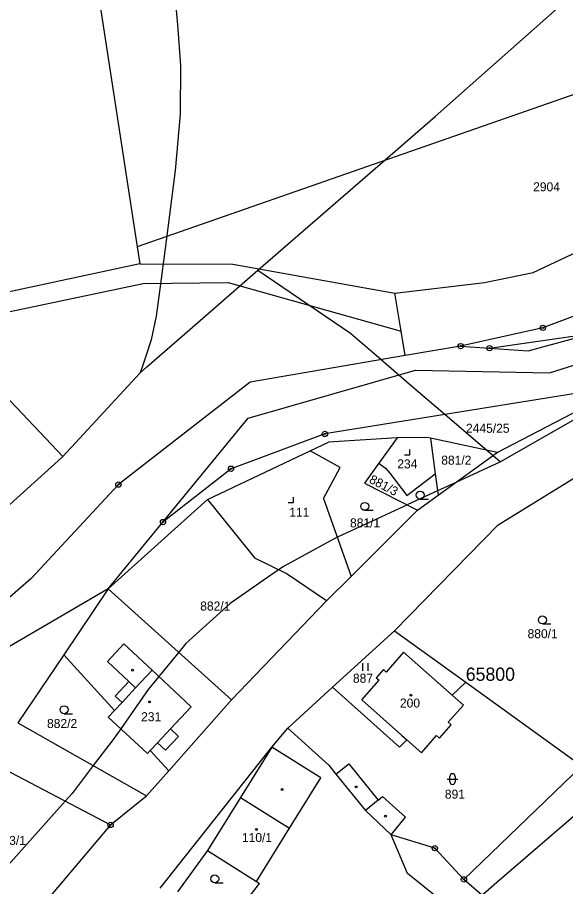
# Model space of a CAD drawing. Extents: x -546762 to -540209, y -1046851 to -1035694.
# Drawn here: x -542845.1 to -542741.6, y -1040039.2 to -1039875.2 of the extents above; entities that cross this region are included whole.
import ezdxf

# ---------------------------------------------------------------- set-up
doc = ezdxf.new("R2010")
doc.units = 0
for name, color, linetype in [('Vrstva 1', 7, 'Continuous'), ('Vrstva 18', 7, 'Continuous'), ('Vrstva 19', 7, 'Continuous'), ('Vrstva 24', 7, 'Continuous'), ('Vrstva 25', 7, 'Continuous'), ('Vrstva 3', 7, 'Continuous'), ('Vrstva 37', 7, 'Continuous'), ('Vrstva 4', 7, 'Continuous'), ('Vrstva 52', 7, 'Continuous'), ('Vrstva 53', 7, 'Continuous'), ('Vrstva 6', 7, 'Continuous')]:
    doc.layers.add(name, color=color, linetype=linetype)

msp = doc.modelspace()

# ---------------------------------------------------------------- linework, layer by layer
at = {"layer": 'Vrstva 1'}
for p, q in [((-542755.98, -1039937.61), (-542739.34, -1039935.24)), ((-542761.42, -1039937.23), (-542755.98, -1039937.61)), ((-542755.98, -1039937.61), (-542748.71, -1039938.12)), ((-542739.39, -1039946.11), (-542787.04, -1039953.79)), ((-542817.6, -1039970.43), (-542801.51, -1039950.85)), ((-542787.04, -1039953.79), (-542804.76, -1039960.36)), ((-542804.76, -1039960.36), (-542817.6, -1039970.43)), ((-542827.95, -1039983.03), (-542817.6, -1039970.43)), ((-542760.47, -1040000.62), (-542763, -1040003.11)), ((-542763, -1040003.11), (-542764.66, -1040001.64)), ((-542760.9, -1040004.95), (-542763, -1040003.11)), ((-542763.76, -1040008.2), (-542760.9, -1040004.95)), ((-542765.4, -1040011.19), (-542763.2, -1040008.7)), ((-542763.2, -1040008.7), (-542763.76, -1040008.2)), ((-542772.95, -1040012.9), (-542771.56, -1040011.53)), ((-542772.58, -1040010.63), (-542771.56, -1040011.53)), ((-542771.56, -1040011.53), (-542768.83, -1040013.95)), ((-542768.83, -1040013.95), (-542765.96, -1040010.69)), ((-542765.96, -1040010.69), (-542765.4, -1040011.19)), ((-542774.55, -1040029.45), (-542771.8, -1040026.09))]:
    msp.add_line(p, q, dxfattribs=at)
for points in [[(-542831.63, -1039858.72), (-542822.48, -1039918.48)], [(-542702.85, -1039876.81), (-542822.48, -1039918.48)], [(-542747.73, -1039923.37), (-542700.61, -1039901.21)], [(-542822.48, -1039918.48), (-542821.99, -1039921.7)], [(-542821.99, -1039921.7), (-542873.31, -1039932.69)], [(-542821.99, -1039921.7), (-542804.44, -1039921.76)], [(-542804.44, -1039921.76), (-542773.83, -1039927.24)], [(-542756.9, -1039925.21), (-542747.73, -1039923.37)], [(-542716.91, -1039922.89), (-542745.9, -1039933.78)], [(-542871.92, -1039936.07), (-542821.34, -1039925.42)], [(-542821.34, -1039925.42), (-542805.31, -1039925.22)], [(-542805.31, -1039925.22), (-542772.67, -1039934.41)], [(-542773.83, -1039927.24), (-542756.9, -1039925.21)], [(-542772.67, -1039934.41), (-542773.83, -1039927.24)], [(-542748.71, -1039938.12), (-542716.54, -1039929.35)], [(-542744.68, -1039942.26), (-542711.55, -1039931.8)], [(-542771.9, -1039939.02), (-542772.67, -1039934.41)], [(-542745.9, -1039933.78), (-542761.42, -1039937.23)], [(-542761.42, -1039937.23), (-542771.9, -1039939.02)], [(-542771.9, -1039939.02), (-542801.12, -1039944.01)], [(-542754.5, -1039957.29), (-542721.64, -1039940.21)], [(-542801.51, -1039950.85), (-542769.96, -1039941.77)], [(-542769.96, -1039941.77), (-542744.68, -1039942.26)], [(-542801.12, -1039944.01), (-542826.01, -1039963.35)], [(-542773.43, -1039954.55), (-542786.37, -1039955.37)], [(-542773.43, -1039954.55), (-542776.88, -1039959.34)], [(-542767.68, -1039954.46), (-542773.43, -1039954.55)], [(-542767.11, -1039954.58), (-542767.68, -1039954.46)], [(-542754.5, -1039957.29), (-542767.11, -1039954.58)], [(-542767.11, -1039954.58), (-542766.2, -1039961.33)], [(-542789.83, -1039957.01), (-542786.37, -1039955.37)], [(-542809.2, -1039966.19), (-542789.83, -1039957.01)], [(-542784.13, -1039960.12), (-542789.83, -1039957.01)], [(-542765.66, -1039965.35), (-542754.5, -1039957.29)], [(-542776.88, -1039959.34), (-542775.58, -1039960.24)], [(-542787.31, -1039965.95), (-542784.13, -1039960.12)], [(-542775.58, -1039960.24), (-542774.79, -1039961.19)], [(-542774.79, -1039961.19), (-542771.59, -1039965.41)], [(-542754.34, -1039970.96), (-542736.82, -1039960.13)], [(-542771.59, -1039965.41), (-542766.2, -1039961.33)], [(-542766.2, -1039961.33), (-542765.66, -1039965.35)], [(-542826.01, -1039963.35), (-542842.47, -1039981.08)], [(-542827.95, -1039983.03), (-542809.2, -1039966.19)], [(-542809.2, -1039966.19), (-542800.28, -1039977.24)], [(-542787.31, -1039965.95), (-542782.07, -1039980.67)], [(-542769.54, -1039968.15), (-542765.66, -1039965.35)], [(-542782.07, -1039980.67), (-542769.54, -1039968.15)], [(-542773.88, -1039990.93), (-542754.34, -1039970.96)], [(-542794.36, -1039980.15), (-542800.28, -1039977.24)], [(-542786.71, -1039985.31), (-542794.36, -1039980.15)], [(-542786.71, -1039985.31), (-542782.07, -1039980.67)], [(-542842.47, -1039981.08), (-542863.14, -1039999.04)], [(-542827.95, -1039983.03), (-542863, -1040003.43)], [(-542827.95, -1039983.03), (-542836.32, -1039995.46)], [(-542804.66, -1040003.95), (-542827.95, -1039983.03)], [(-542804.66, -1040003.95), (-542786.71, -1039985.31)], [(-542785.63, -1040001.57), (-542773.88, -1039990.93)], [(-542773.88, -1039990.93), (-542760.47, -1040000.62)], [(-542836.32, -1039995.46), (-542844.98, -1040008.3)], [(-542836.32, -1039995.46), (-542826.78, -1040006)], [(-542772.19, -1039995), (-542775.45, -1039998.72)], [(-542772.19, -1039995), (-542764.66, -1040001.64)], [(-542775.98, -1039998.26), (-542777.35, -1039999.79)], [(-542775.45, -1039998.72), (-542775.98, -1039998.26)], [(-542780.09, -1040003.98), (-542776.81, -1040000.26)], [(-542777.35, -1039999.79), (-542776.81, -1040000.26)], [(-542760.47, -1040000.62), (-542740.08, -1040015.35)], [(-542794.04, -1040009.29), (-542785.63, -1040001.57)], [(-542772.95, -1040012.9), (-542785.63, -1040001.57)], [(-542816.52, -1040017.35), (-542804.66, -1040003.95)], [(-542772.58, -1040010.63), (-542780.09, -1040003.98)], [(-542827.93, -1040007.23), (-542826.78, -1040006)], [(-542844.98, -1040008.3), (-542820.69, -1040022.07)], [(-542820.54, -1040014.1), (-542827.93, -1040007.23)], [(-542797.08, -1040012.91), (-542794.04, -1040009.29)], [(-542794.04, -1040009.29), (-542786.33, -1040016.3)], [(-542854.07, -1040013.63), (-542827.49, -1040027.57)], [(-542819.99, -1040013.51), (-542820.54, -1040014.1)], [(-542819.99, -1040013.51), (-542816.52, -1040017.35)], [(-542818.13, -1040039.5), (-542797.08, -1040012.91)], [(-542786.33, -1040016.3), (-542784.95, -1040018.01)], [(-542784.95, -1040018.01), (-542782.54, -1040016.06)], [(-542782.54, -1040016.06), (-542777, -1040022.9)], [(-542738.58, -1040016.43), (-542760.8, -1040037.84)], [(-542820.69, -1040022.07), (-542816.52, -1040017.35)], [(-542827.49, -1040027.57), (-542820.69, -1040022.07)], [(-542777, -1040022.9), (-542776.14, -1040022.21)], [(-542776.14, -1040022.21), (-542771.8, -1040026.09)], [(-542827.49, -1040027.57), (-542845.99, -1040049.42)], [(-542766.3, -1040031.96), (-542774.55, -1040029.45)], [(-542771.43, -1040036.71), (-542774.55, -1040029.45)], [(-542809.19, -1040032.37), (-542814.84, -1040040.17)], [(-542809.19, -1040032.37), (-542799.97, -1040038.21)], [(-542760.8, -1040037.84), (-542766.3, -1040031.96)], [(-542765.64, -1040041.36), (-542771.43, -1040036.71)], [(-542799.97, -1040038.21), (-542799.37, -1040038.59)], [(-542746.73, -1040050.07), (-542760.8, -1040037.84)], [(-542805.78, -1040046.95), (-542799.37, -1040038.59)]]:
    msp.add_lwpolyline(points, dxfattribs=at)
at = {"layer": 'Vrstva 24'}
for centre, radius in [((-542745.9, -1039933.78), 0.5), ((-542745.9, -1039933.78), 0.1), ((-542761.42, -1039937.23), 0.5), ((-542761.42, -1039937.23), 0.1), ((-542755.98, -1039937.61), 0.5), ((-542755.98, -1039937.61), 0.1), ((-542787.04, -1039953.79), 0.5), ((-542787.04, -1039953.79), 0.1), ((-542804.76, -1039960.36), 0.5), ((-542804.76, -1039960.36), 0.1), ((-542826.01, -1039963.35), 0.5), ((-542826.01, -1039963.35), 0.1), ((-542817.6, -1039970.43), 0.5), ((-542817.6, -1039970.43), 0.1), ((-542827.49, -1040027.57), 0.5), ((-542827.49, -1040027.57), 0.1), ((-542766.3, -1040031.96), 0.5), ((-542766.3, -1040031.96), 0.1), ((-542760.8, -1040037.84), 0.5), ((-542760.8, -1040037.84), 0.1)]:
    msp.add_circle(centre, radius, dxfattribs=at)
at = {"layer": 'Vrstva 25'}
for p, q in [((-542769.06, -1039966.08), (-542767.46, -1039966.08)), ((-542779.53, -1039968.21), (-542777.93, -1039968.21)), ((-542746, -1039989.64), (-542744.4, -1039989.64)), ((-542779.89, -1039998.52), (-542779.89, -1039997.02)), ((-542778.89, -1039998.52), (-542778.89, -1039997.02)), ((-542836.27, -1040006.58), (-542834.67, -1040006.58)), ((-542763.46, -1040019.41), (-542763.46, -1040018.41)), ((-542762.46, -1040018.41), (-542762.46, -1040019.41)), ((-542763.96, -1040018.91), (-542761.96, -1040018.91)), ((-542807.83, -1040038.49), (-542806.23, -1040038.49))]:
    msp.add_line(p, q, dxfattribs=at)
for points in [[(-542772.03, -1039957.71), (-542771.03, -1039957.71), (-542771.03, -1039956.71)], [(-542793.96, -1039966.72), (-542792.96, -1039966.72), (-542792.96, -1039965.72)]]:
    msp.add_lwpolyline(points, dxfattribs=at)
for centre, radius in [((-542769.06, -1039965.33), 0.75), ((-542779.53, -1039967.46), 0.75), ((-542746, -1039988.89), 0.75), ((-542823.37, -1039998.35), 0.175), ((-542770.8, -1040003.11), 0.175), ((-542836.27, -1040005.83), 0.75), ((-542820.13, -1040004.36), 0.175), ((-542781.13, -1040020.4), 0.175), ((-542795.13, -1040020.87), 0.175), ((-542775.62, -1040025.91), 0.175), ((-542799.97, -1040028.41), 0.175), ((-542807.83, -1040037.74), 0.75)]:
    msp.add_circle(centre, radius, dxfattribs=at)
for centre, start, end in [((-542762.96, -1040018.41), 0, 180), ((-542762.96, -1040019.41), 180, 0)]:
    msp.add_arc(centre, 0.5, start, end, dxfattribs=at)
at = {"layer": 'Vrstva 3'}
for points in [[(-542772.19, -1039995), (-542775.45, -1039998.72)], [(-542772.19, -1039995), (-542764.66, -1040001.64)], [(-542822.78, -1040001.71), (-542819.66, -1039998.37)], [(-542819.66, -1039998.37), (-542812.31, -1040005.26)], [(-542775.98, -1039998.26), (-542777.35, -1039999.79)], [(-542775.45, -1039998.72), (-542775.98, -1039998.26)], [(-542780.09, -1040003.98), (-542776.81, -1040000.26)], [(-542777.35, -1039999.79), (-542776.81, -1040000.26)], [(-542825.33, -1040004.45), (-542822.78, -1040001.71)], [(-542763, -1040003.11), (-542764.66, -1040001.64)], [(-542760.9, -1040004.95), (-542763, -1040003.11)], [(-542826.78, -1040006), (-542825.33, -1040004.45)], [(-542812.31, -1040005.26), (-542816.2, -1040009.44)], [(-542772.58, -1040010.63), (-542780.09, -1040003.98)], [(-542763.76, -1040008.2), (-542760.9, -1040004.95)], [(-542827.93, -1040007.23), (-542826.78, -1040006)], [(-542820.54, -1040014.1), (-542827.93, -1040007.23)], [(-542765.4, -1040011.19), (-542763.2, -1040008.7)], [(-542763.2, -1040008.7), (-542763.76, -1040008.2)], [(-542816.2, -1040009.44), (-542818.63, -1040012.05)], [(-542818.63, -1040012.05), (-542819.99, -1040013.51)], [(-542772.58, -1040010.63), (-542771.56, -1040011.53)], [(-542771.56, -1040011.53), (-542768.83, -1040013.95)], [(-542768.83, -1040013.95), (-542765.96, -1040010.69)], [(-542765.96, -1040010.69), (-542765.4, -1040011.19)], [(-542819.99, -1040013.51), (-542820.54, -1040014.1)], [(-542803, -1040022.42), (-542809.19, -1040032.37)], [(-542803, -1040022.42), (-542793.73, -1040028.19)], [(-542799.97, -1040038.21), (-542793.73, -1040028.19)], [(-542809.19, -1040032.37), (-542799.97, -1040038.21)]]:
    msp.add_lwpolyline(points, dxfattribs=at)
at = {"layer": 'Vrstva 37'}
for centre in [(-542770.8, -1040003.11), (-542820.13, -1040004.36), (-542799.97, -1040028.41)]:
    msp.add_circle(centre, 0.175, dxfattribs=at)
at = {"layer": 'Vrstva 4'}
msp.add_line((-542779.41, -1040024.85), (-542774.55, -1040029.45), dxfattribs=at)
for points in [[(-542828.09, -1039996.73), (-542824.97, -1039993.4)], [(-542824.97, -1039993.4), (-542819.66, -1039998.37)], [(-542824.05, -1040000.52), (-542828.09, -1039996.73)], [(-542822.78, -1040001.71), (-542819.66, -1039998.37)], [(-542819.66, -1039998.37), (-542812.31, -1040005.26)], [(-542824.05, -1040000.52), (-542826.61, -1040003.26)], [(-542822.78, -1040001.71), (-542824.05, -1040000.52)], [(-542825.33, -1040004.45), (-542822.78, -1040001.71)], [(-542826.61, -1040003.26), (-542825.33, -1040004.45)], [(-542826.78, -1040006), (-542825.33, -1040004.45)], [(-542812.31, -1040005.26), (-542816.2, -1040009.44)], [(-542816.2, -1040009.44), (-542818.63, -1040012.05)], [(-542814.67, -1040010.86), (-542816.2, -1040009.44)], [(-542818.63, -1040012.05), (-542819.99, -1040013.51)], [(-542817.1, -1040013.47), (-542818.63, -1040012.05)], [(-542817.1, -1040013.47), (-542814.67, -1040010.86)], [(-542797.08, -1040012.91), (-542803, -1040022.42)], [(-542787.81, -1040018.68), (-542797.08, -1040012.91)], [(-542784.95, -1040018.01), (-542779.41, -1040024.85)], [(-542793.73, -1040028.19), (-542787.81, -1040018.68)], [(-542803, -1040022.42), (-542809.19, -1040032.37)], [(-542803, -1040022.42), (-542793.73, -1040028.19)], [(-542777, -1040022.9), (-542779.41, -1040024.85)], [(-542799.97, -1040038.21), (-542793.73, -1040028.19)]]:
    msp.add_lwpolyline(points, dxfattribs=at)
at = {"layer": 'Vrstva 52'}
for points in [[(-542799.7, -1039922.92), (-542766.24, -1039893.88), (-542718.4, -1039851.52), (-542716.86, -1039850.04), (-542705.95, -1039839.57), (-542701.66, -1039835.46), (-542696.42, -1039830.43), (-542692.73, -1039826.9), (-542688.04, -1039821.34), (-542674.17, -1039804.93), (-542667.3, -1039795.89), (-542666.74, -1039795.15), (-542662.79, -1039789.96), (-542661.5, -1039788.26), (-542660.05, -1039786.36), (-542658.15, -1039783.99), (-542652.27, -1039776.67), (-542648.29, -1039771.72), (-542645.15, -1039767.8), (-542640.36, -1039762.76), (-542631.55, -1039753.5), (-542628.91, -1039750.73), (-542627.53, -1039749.28)], [(-542818.36, -1039852.76), (-542816.32, -1039861.42), (-542815.63, -1039868.34), (-542814.87, -1039876.62), (-542814.27, -1039884.31), (-542814.35, -1039893.44), (-542815.29, -1039904.12), (-542817.08, -1039917.86), (-542818.25, -1039926.9), (-542818.86, -1039931.59), (-542819.85, -1039936.07), (-542820.83, -1039939.15), (-542821.28, -1039940.46), (-542821.91, -1039942.27)], [(-542902.1, -1039907.64), (-542889.06, -1039912.68), (-542879.5, -1039917.76), (-542869.64, -1039924.34), (-542861.57, -1039931.22), (-542856.17, -1039937.26), (-542855.32, -1039938.21), (-542849.78, -1039944.07), (-542839.8, -1039954.61), (-542836.51, -1039958.08)], [(-542820.63, -1039941.15), (-542811.06, -1039932.81), (-542799.7, -1039922.92)], [(-542799.7, -1039922.92), (-542782.2, -1039934.76), (-542777.34, -1039938.96), (-542773.06, -1039942.66), (-542771.14, -1039944.32), (-542764.34, -1039950.13), (-542756.45, -1039956.87), (-542755.29, -1039957.86), (-542753.9, -1039959.04)], [(-542821.91, -1039942.27), (-542820.63, -1039941.15)], [(-542835.1, -1039956.57), (-542834.85, -1039956.3), (-542821.91, -1039942.27)], [(-542735.08, -1039948.31), (-542753.9, -1039959.04)], [(-542836.51, -1039958.08), (-542835.1, -1039956.57)], [(-542890.37, -1040010.39), (-542889.83, -1040009.88), (-542877.8, -1039997.58), (-542869.87, -1039989.23), (-542862.9, -1039981.89), (-542836.66, -1039958.24), (-542836.51, -1039958.08)], [(-542753.9, -1039959.04), (-542762.31, -1039962.93), (-542765.77, -1039964.53), (-542771.41, -1039967.14), (-542771.47, -1039967.17), (-542784.56, -1039973.22), (-542784.7, -1039973.29), (-542794.75, -1039978.72), (-542795.8, -1039979.44), (-542804.95, -1039985.78), (-542813.31, -1039993.36), (-542814.64, -1039994.99), (-542820.37, -1040001.99), (-542825.58, -1040009.41), (-542827.17, -1040011.67), (-542830.75, -1040016.37), (-542834.75, -1040021.61), (-542836.05, -1040023.08), (-542847.3, -1040035.73)], [(-542711.79, -1040001.59), (-542733.4, -1040020.17), (-542754.62, -1040038.42), (-542757.69, -1040041.16), (-542760.79, -1040043.92), (-542776.43, -1040057.86), (-542781.02, -1040061.95), (-542794.66, -1040075.13), (-542797.26, -1040077.64), (-542803.76, -1040083.92), (-542810.64, -1040090.85), (-542814.58, -1040094.82), (-542837.23, -1040117.64), (-542838.47, -1040118.89), (-542840.1, -1040120.54), (-542842.09, -1040122.56)]]:
    msp.add_lwpolyline(points, dxfattribs=at)
at = {"layer": 'Vrstva 6'}
for points in [[(-542776.88, -1039959.34), (-542779.57, -1039963.07)], [(-542779.57, -1039963.07), (-542769.54, -1039968.15)]]:
    msp.add_lwpolyline(points, dxfattribs=at)

# ---------------------------------------------------------------- texts
at = {"layer": 'Vrstva 18'}
for s, p in [('2904', (-542747.74, -1039908.02)), ('2445/25', (-542760.41, -1039953.58)), ('881/2', (-542765.08, -1039959.6)), ('881/1', (-542782.3, -1039971.43)), ('882/1', (-542810.57, -1039987.12)), ('880/1', (-542748.79, -1039992.34)), ('887', (-542781.75, -1040000.74)), ('882/2', (-542839.48, -1040009.28)), ('891', (-542764.4, -1040022.61)), ('883/1', (-542849.16, -1040031.34))]:
    msp.add_text(s, height=1.7, dxfattribs=at).set_placement(p)
msp.add_text('881/3', height=1.7, rotation=332.2811, dxfattribs=at).set_placement((-542778.84, -1039962.91))
at = {"layer": 'Vrstva 19'}
for s, p in [('234', (-542773.38, -1039960.3)), ('111', (-542793.76, -1039969.42)), ('200', (-542772.88, -1040005.42)), ('231', (-542821.73, -1040008)), ('110/1', (-542802.7, -1040030.8))]:
    msp.add_text(s, height=1.7, dxfattribs=at).set_placement(p)
at = {"layer": 'Vrstva 53'}
msp.add_text('65800', height=2.5, dxfattribs=at).set_placement((-542760.46, -1040000.38))

doc.saveas('drawing.dxf')
